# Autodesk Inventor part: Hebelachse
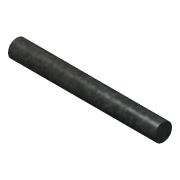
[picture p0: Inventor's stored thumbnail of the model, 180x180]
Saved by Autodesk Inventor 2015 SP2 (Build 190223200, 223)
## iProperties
Created: 2017-07
Material: St
Document SubType Name: Modeling
Designer: N.Krebs
Density: 7.85 g/cm^3
Appearance: Platte
Part Number: Hebelachse
Mass: 7.70192 g
Surface Area: 8.20883 cm^2
Volume: 0.981136 cm^3
Author: krebs
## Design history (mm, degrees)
sketch "Skizze1"
  geometry: L1 (-25, 3)-(25, 3); L2 (25, 3)-(25, 0); L3 (25, 0)-(-25, 0); L4 (-25, 0)-(-25, 3); 2 further points
  constraints: 8 end point, 2 parallel, 1 coincident, 1 horizontal, 1 midpoint, 1 perpendicular
  dimensions: "d8" = 6 diameter of L1 L3; "d9" = 50 distance between parallel lines of L2 L4
revolve "Umdrehung2" sketch "Skizze1" stored, may be unused: angle "d10" = 90 deg
chamfer "Fase1" distance "d3" = 0.2; stored, may be unused: second distance "d4" = 2, angle "d5" = 45 deg
node "Mittelebene"
node "Volumenkörper1"
node "Volumenkörper2"
